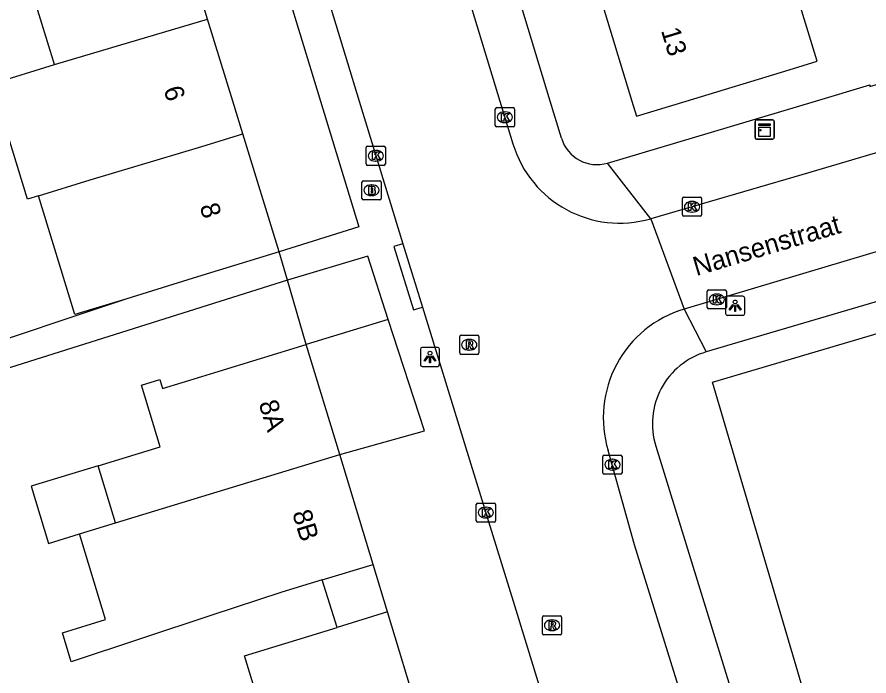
# Model space of a CAD drawing. Extents: x 161253 to 161848, y 384872 to 385383.
# Drawn here: x 161490.34 to 161534.89, y 384969.95 to 385004.39 of the extents above; entities that cross this region are included whole.
import ezdxf

# ---------------------------------------------------------------- set-up
doc = ezdxf.new("R2010")
doc.units = 0
for name, color, linetype in [('IMGEO_Brandkraan', 7, 'Continuous'), ('IMGEO_Hek', 7, 'Continuous'), ('IMGEO_Kast', 7, 'Continuous'), ('IMGEO_Kolk', 7, 'Continuous'), ('IMGEO_Lichtpunt', 7, 'Continuous'), ('IMGEO_Openbare_ruimte_label', 7, 'Continuous'), ('IMGEO_Pand', 7, 'Continuous'), ('IMGEO_Pand_nummerreeks', 7, 'Continuous'), ('IMGEO_Rijbaan_lokaal_open', 7, 'Continuous'), ('IMGEO_Rioolput', 7, 'Continuous'), ('IMGEO_Voetpad_open', 7, 'Continuous')]:
    doc.layers.add(name, color=color, linetype=linetype)

msp = doc.modelspace()

# ---------------------------------------------------------------- linework, layer by layer
at = {"layer": 'IMGEO_Brandkraan'}
for p, q in [((161508.378, 384994.912), (161508.378, 384995.764)), ((161508.453, 384995.838), (161509.305, 384995.838)), ((161509.379, 384995.764), (161509.379, 384994.912)), ((161508.866, 384995.618), (161508.891, 384995.618)), ((161509.305, 384994.838), (161508.453, 384994.838)), ((161508.889, 384995.058), (161508.864, 384995.058))]:
    msp.add_line(p, q, dxfattribs=at)
for points in [[(161508.378, 384994.912), (161508.378, 384995.764)], [(161508.453, 384995.838), (161509.305, 384995.838)], [(161509.379, 384995.764), (161509.379, 384994.912)], [(161508.726, 384995.538), (161508.726, 384995.138), (161508.939, 384995.138)], [(161508.957, 384995.538), (161508.726, 384995.538)], [(161508.905, 384995.457), (161508.851, 384995.457), (161508.851, 384995.381)], [(161508.851, 384995.381), (161508.904, 384995.381)], [(161508.913, 384995.305), (161508.851, 384995.305), (161508.851, 384995.224)], [(161508.851, 384995.224), (161508.913, 384995.224)], [(161509.305, 384994.838), (161508.453, 384994.838)]]:
    msp.add_lwpolyline(points, dxfattribs=at)
for centre, radius, start, end in [((161508.455, 384995.762), 0.0765, 91.552, 178.448), ((161508.455, 384995.762), 0.0765, 91.552, 178.448), ((161509.303, 384995.762), 0.0765, 1.552, 88.448), ((161509.303, 384995.762), 0.0765, 1.552, 88.448), ((161508.906, 384995.419), 0.0379, 267.8285, 90.9355), ((161508.914, 384995.264), 0.0404, 269.8759, 90.5077), ((161508.961, 384995.393), 0.145, 59.4692, 91.5367), ((161508.986, 384995.44), 0.0922, 285.5137, 58.1501), ((161508.991, 384995.248), 0.105, 301.3115, 78.989), ((161508.455, 384994.914), 0.0765, 181.552, 268.448), ((161508.455, 384994.914), 0.0765, 181.552, 268.448), ((161508.945, 384995.389), 0.251, 268.6676, 293.5347), ((161509.303, 384994.914), 0.0765, 271.552, 358.448), ((161509.303, 384994.914), 0.0765, 271.552, 358.448)]:
    msp.add_arc(centre, radius, start, end, dxfattribs=at)
for centre, major_axis, ratio, start_param, end_param in [((161508.865, 384995.338), (-0.387, 0.002), 0.722429, 4.712389, 7.853982), ((161508.89, 384995.338), (-0.39, 0.002), 0.717154, 1.570796, 4.712389)]:
    msp.add_ellipse(centre, major_axis=major_axis, ratio=ratio, start_param=start_param, end_param=end_param, dxfattribs=at)
at = {"layer": 'IMGEO_Hek'}
msp.add_lwpolyline([(161507.075, 384972.487), (161506.304, 384974.971)], dxfattribs=at)
at = {"layer": 'IMGEO_Kast'}
for p, q in [((161528.929, 384998.089), (161528.929, 384998.93)), ((161528.929, 384998.93), (161528.929, 384998.089)), ((161529.004, 384999.014), (161529.845, 384999.014)), ((161529.845, 384999.014), (161529.004, 384999.014)), ((161529.929, 384998.939), (161529.929, 384998.098)), ((161529.929, 384998.098), (161529.929, 384998.939)), ((161529.854, 384998.014), (161529.013, 384998.014)), ((161529.013, 384998.014), (161529.854, 384998.014))]:
    msp.add_line(p, q, dxfattribs=at)
for points in [[(161529.124, 384998.804), (161529.724, 384998.804), (161529.724, 384998.719), (161529.124, 384998.719), (161529.124, 384998.804)], [(161529.124, 384998.629), (161529.724, 384998.629), (161529.724, 384998.14), (161529.124, 384998.14), (161529.124, 384998.629)]]:
    msp.add_lwpolyline(points, dxfattribs=at)
msp.add_circle((161529.208, 384998.478), 0.0377, dxfattribs=at)
for centre, start, end in [((161529.007, 384998.936), 92.4484, 184.2845), ((161529.007, 384998.936), 92.4484, 184.2845), ((161529.851, 384998.936), 2.4484, 94.2845), ((161529.851, 384998.936), 2.4484, 94.2845), ((161529.007, 384998.092), 182.4484, 274.2845), ((161529.007, 384998.092), 182.4484, 274.2845), ((161529.851, 384998.092), 272.4484, 4.2845), ((161529.851, 384998.092), 272.4484, 4.2845)]:
    msp.add_arc(centre, 0.0779, start, end, dxfattribs=at)
at = {"layer": 'IMGEO_Kolk'}
for p, q in [((161515.425, 384999.657), (161516.277, 384999.657)), ((161515.35, 384998.731), (161515.35, 384999.583)), ((161515.838, 384999.437), (161515.863, 384999.437)), ((161516.351, 384999.583), (161516.351, 384998.731)), ((161515.861, 384998.877), (161515.836, 384998.877)), ((161516.277, 384998.657), (161515.425, 384998.657)), ((161508.601, 384996.714), (161508.601, 384997.566)), ((161508.676, 384997.64), (161509.528, 384997.64)), ((161509.602, 384997.566), (161509.602, 384996.714)), ((161509.089, 384997.42), (161509.114, 384997.42)), ((161509.528, 384996.64), (161508.676, 384996.64)), ((161509.112, 384996.86), (161509.087, 384996.86)), ((161525.134, 384994.051), (161525.134, 384994.903)), ((161525.209, 384994.977), (161526.061, 384994.977)), ((161525.622, 384994.757), (161525.647, 384994.757)), ((161526.135, 384994.903), (161526.135, 384994.051)), ((161526.061, 384993.977), (161525.209, 384993.977)), ((161525.645, 384994.197), (161525.62, 384994.197)), ((161526.431, 384989.209), (161526.431, 384990.061)), ((161526.506, 384990.135), (161527.358, 384990.135)), ((161526.919, 384989.915), (161526.944, 384989.915)), ((161527.432, 384990.061), (161527.432, 384989.209)), ((161527.358, 384989.135), (161526.506, 384989.135)), ((161526.942, 384989.355), (161526.917, 384989.355)), ((161520.973, 384980.571), (161520.973, 384981.423)), ((161521.048, 384981.497), (161521.9, 384981.497)), ((161521.974, 384981.423), (161521.974, 384980.571)), ((161521.461, 384981.277), (161521.486, 384981.277)), ((161521.484, 384980.717), (161521.459, 384980.717)), ((161521.9, 384980.497), (161521.048, 384980.497)), ((161514.356, 384978.066), (161514.356, 384978.918)), ((161514.431, 384978.992), (161515.283, 384978.992)), ((161514.844, 384978.772), (161514.869, 384978.772)), ((161515.357, 384978.918), (161515.357, 384978.066)), ((161515.283, 384977.992), (161514.431, 384977.992)), ((161514.867, 384978.212), (161514.842, 384978.212))]:
    msp.add_line(p, q, dxfattribs=at)
for points in [[(161515.425, 384999.657), (161516.277, 384999.657)], [(161515.35, 384998.731), (161515.35, 384999.583)], [(161515.671, 384999.357), (161515.794, 384999.357), (161515.794, 384999.206), (161515.924, 384999.357), (161516.088, 384999.357), (161515.942, 384999.206), (161516.095, 384998.957), (161515.943, 384998.957), (161515.858, 384999.121), (161515.794, 384999.054), (161515.794, 384998.957), (161515.671, 384998.957), (161515.671, 384999.357)], [(161516.351, 384999.583), (161516.351, 384998.731)], [(161516.277, 384998.657), (161515.425, 384998.657)], [(161508.601, 384996.714), (161508.601, 384997.566)], [(161508.676, 384997.64), (161509.528, 384997.64)], [(161509.602, 384997.566), (161509.602, 384996.714)], [(161508.922, 384997.34), (161509.045, 384997.34), (161509.045, 384997.189), (161509.175, 384997.34), (161509.339, 384997.34), (161509.193, 384997.189), (161509.346, 384996.94), (161509.194, 384996.94), (161509.109, 384997.104), (161509.045, 384997.037), (161509.045, 384996.94), (161508.922, 384996.94), (161508.922, 384997.34)], [(161509.528, 384996.64), (161508.676, 384996.64)], [(161525.134, 384994.051), (161525.134, 384994.903)], [(161525.209, 384994.977), (161526.061, 384994.977)], [(161526.135, 384994.903), (161526.135, 384994.051)], [(161525.455, 384994.677), (161525.578, 384994.677), (161525.578, 384994.526), (161525.708, 384994.677), (161525.872, 384994.677), (161525.726, 384994.526), (161525.879, 384994.277), (161525.727, 384994.277), (161525.642, 384994.441), (161525.578, 384994.374), (161525.578, 384994.277), (161525.455, 384994.277), (161525.455, 384994.677)], [(161526.061, 384993.977), (161525.209, 384993.977)], [(161526.431, 384989.209), (161526.431, 384990.061)], [(161526.506, 384990.135), (161527.358, 384990.135)], [(161527.432, 384990.061), (161527.432, 384989.209)], [(161526.752, 384989.835), (161526.875, 384989.835), (161526.875, 384989.684), (161527.005, 384989.835), (161527.169, 384989.835), (161527.023, 384989.684), (161527.176, 384989.435), (161527.024, 384989.435), (161526.939, 384989.599), (161526.875, 384989.532), (161526.875, 384989.435), (161526.752, 384989.435), (161526.752, 384989.835)], [(161527.358, 384989.135), (161526.506, 384989.135)], [(161520.973, 384980.571), (161520.973, 384981.423)], [(161521.048, 384981.497), (161521.9, 384981.497)], [(161521.974, 384981.423), (161521.974, 384980.571)], [(161521.294, 384981.197), (161521.417, 384981.197), (161521.417, 384981.046), (161521.547, 384981.197), (161521.711, 384981.197), (161521.565, 384981.046), (161521.718, 384980.797), (161521.566, 384980.797), (161521.481, 384980.961), (161521.417, 384980.894), (161521.417, 384980.797), (161521.294, 384980.797), (161521.294, 384981.197)], [(161521.9, 384980.497), (161521.048, 384980.497)], [(161514.356, 384978.066), (161514.356, 384978.918)], [(161514.431, 384978.992), (161515.283, 384978.992)], [(161515.357, 384978.918), (161515.357, 384978.066)], [(161514.677, 384978.692), (161514.8, 384978.692), (161514.8, 384978.541), (161514.93, 384978.692), (161515.094, 384978.692), (161514.948, 384978.541), (161515.101, 384978.292), (161514.949, 384978.292), (161514.864, 384978.456), (161514.8, 384978.389), (161514.8, 384978.292), (161514.677, 384978.292), (161514.677, 384978.692)], [(161515.283, 384977.992), (161514.431, 384977.992)]]:
    msp.add_lwpolyline(points, dxfattribs=at)
for centre, start, end in [((161515.427, 384999.581), 91.552, 178.448), ((161515.427, 384999.581), 91.552, 178.448), ((161516.275, 384999.581), 1.552, 88.448), ((161516.275, 384999.581), 1.552, 88.448), ((161515.427, 384998.733), 181.552, 268.448), ((161515.427, 384998.733), 181.552, 268.448), ((161516.275, 384998.733), 271.552, 358.448), ((161516.275, 384998.733), 271.552, 358.448), ((161508.678, 384997.564), 91.552, 178.448), ((161508.678, 384997.564), 91.552, 178.448), ((161509.526, 384997.564), 1.552, 88.448), ((161509.526, 384997.564), 1.552, 88.448), ((161508.678, 384996.716), 181.552, 268.448), ((161508.678, 384996.716), 181.552, 268.448), ((161509.526, 384996.716), 271.552, 358.448), ((161509.526, 384996.716), 271.552, 358.448), ((161525.211, 384994.901), 91.552, 178.448), ((161525.211, 384994.901), 91.552, 178.448), ((161526.059, 384994.901), 1.552, 88.448), ((161526.059, 384994.901), 1.552, 88.448), ((161525.211, 384994.053), 181.552, 268.448), ((161525.211, 384994.053), 181.552, 268.448), ((161526.059, 384994.053), 271.552, 358.448), ((161526.059, 384994.053), 271.552, 358.448), ((161526.508, 384990.059), 91.552, 178.448), ((161526.508, 384990.059), 91.552, 178.448), ((161527.356, 384990.059), 1.552, 88.448), ((161527.356, 384990.059), 1.552, 88.448), ((161526.508, 384989.211), 181.552, 268.448), ((161526.508, 384989.211), 181.552, 268.448), ((161527.356, 384989.211), 271.552, 358.448), ((161527.356, 384989.211), 271.552, 358.448), ((161521.05, 384981.421), 91.552, 178.448), ((161521.05, 384981.421), 91.552, 178.448), ((161521.898, 384981.421), 1.552, 88.448), ((161521.898, 384981.421), 1.552, 88.448), ((161521.05, 384980.573), 181.552, 268.448), ((161521.05, 384980.573), 181.552, 268.448), ((161521.898, 384980.573), 271.552, 358.448), ((161521.898, 384980.573), 271.552, 358.448), ((161514.433, 384978.916), 91.552, 178.448), ((161514.433, 384978.916), 91.552, 178.448), ((161515.281, 384978.916), 1.552, 88.448), ((161515.281, 384978.916), 1.552, 88.448), ((161514.433, 384978.068), 181.552, 268.448), ((161514.433, 384978.068), 181.552, 268.448), ((161515.281, 384978.068), 271.552, 358.448), ((161515.281, 384978.068), 271.552, 358.448)]:
    msp.add_arc(centre, 0.0765, start, end, dxfattribs=at)
for centre, major_axis, ratio, start_param, end_param in [((161515.837, 384999.157), (-0.387, 0.002), 0.722429, 4.712389, 7.853982), ((161515.862, 384999.157), (-0.39, 0.002), 0.717154, 1.570796, 4.712389), ((161509.088, 384997.14), (-0.387, 0.002), 0.722429, 4.712389, 7.853982), ((161509.113, 384997.14), (-0.39, 0.002), 0.717154, 1.570796, 4.712389), ((161525.621, 384994.477), (-0.387, 0.002), 0.722429, 4.712389, 7.853982), ((161525.646, 384994.477), (-0.39, 0.002), 0.717154, 1.570796, 4.712389), ((161526.918, 384989.635), (-0.387, 0.002), 0.722429, 4.712389, 7.853982), ((161526.943, 384989.635), (-0.39, 0.002), 0.717154, 1.570796, 4.712389), ((161521.46, 384980.997), (-0.387, 0.002), 0.722429, 4.712389, 7.853982), ((161521.485, 384980.997), (-0.39, 0.002), 0.717154, 1.570796, 4.712389), ((161514.843, 384978.492), (-0.387, 0.002), 0.722429, 4.712389, 7.853982), ((161514.868, 384978.492), (-0.39, 0.002), 0.717154, 1.570796, 4.712389)]:
    msp.add_ellipse(centre, major_axis=major_axis, ratio=ratio, start_param=start_param, end_param=end_param, dxfattribs=at)
at = {"layer": 'IMGEO_Lichtpunt'}
for p, q in [((161527.393, 384989.703), (161527.393, 384988.896)), ((161527.393, 384989.703), (161527.393, 384988.896)), ((161528.295, 384989.798), (161527.487, 384989.798)), ((161528.295, 384989.798), (161527.487, 384989.798)), ((161528.389, 384988.896), (161528.389, 384989.703)), ((161528.389, 384988.896), (161528.389, 384989.703)), ((161527.487, 384988.802), (161528.295, 384988.802)), ((161527.487, 384988.802), (161528.295, 384988.802)), ((161511.436, 384987.029), (161511.436, 384986.222)), ((161511.436, 384987.029), (161511.436, 384986.222)), ((161512.338, 384987.124), (161511.53, 384987.124)), ((161512.338, 384987.124), (161511.53, 384987.124)), ((161512.432, 384986.222), (161512.432, 384987.029)), ((161512.432, 384986.222), (161512.432, 384987.029)), ((161511.53, 384986.128), (161512.338, 384986.128)), ((161511.53, 384986.128), (161512.338, 384986.128))]:
    msp.add_line(p, q, dxfattribs=at)
for points in [[(161527.767, 384989.367), (161527.806, 384989.339), (161527.618, 384989.077), (161527.58, 384989.104), (161527.767, 384989.367)], [(161527.869, 384989.319), (161527.916, 384989.319), (161527.916, 384988.997), (161527.869, 384988.997), (161527.869, 384989.319)], [(161527.979, 384989.339), (161528.017, 384989.366), (161528.204, 384989.104), (161528.165, 384989.076), (161527.979, 384989.339)], [(161511.81, 384986.693), (161511.849, 384986.665), (161511.661, 384986.403), (161511.623, 384986.43), (161511.81, 384986.693)], [(161511.912, 384986.645), (161511.959, 384986.645), (161511.959, 384986.323), (161511.912, 384986.323), (161511.912, 384986.645)], [(161512.022, 384986.665), (161512.06, 384986.692), (161512.247, 384986.43), (161512.208, 384986.402), (161512.022, 384986.665)]]:
    msp.add_lwpolyline(points, dxfattribs=at)
for centre in [(161527.892, 384989.501), (161511.935, 384986.827)]:
    msp.add_circle(centre, 0.0994, dxfattribs=at)
for centre, start, end in [((161527.487, 384989.703), 90, 180), ((161527.487, 384989.703), 90, 180), ((161528.295, 384989.703), 0, 90), ((161528.295, 384989.703), 0, 90), ((161527.487, 384988.896), 180, 270), ((161527.487, 384988.896), 180, 270), ((161528.295, 384988.896), 270, 0), ((161528.295, 384988.896), 270, 360), ((161511.53, 384987.029), 90, 180), ((161511.53, 384987.029), 90, 180), ((161512.338, 384987.029), 0, 90), ((161512.338, 384987.029), 0, 90), ((161511.53, 384986.222), 180, 270), ((161511.53, 384986.222), 180, 270), ((161512.338, 384986.222), 270, 0), ((161512.338, 384986.222), 270, 360)]:
    msp.add_arc(centre, 0.0946, start, end, dxfattribs=at)
at = {"layer": 'IMGEO_Pand'}
for points in [[(161500.299, 385004.283), (161500, 385005.255), (161498.443, 385010.31)], [(161492.311, 385001.903), (161490.476, 385007.857)], [(161520.856, 385005.389), (161522.493, 385000), (161522.733, 384999.21), (161525.334, 385000), (161530.719, 385001.636), (161532.174, 385002.078), (161531.166, 385005.396), (161529.711, 385004.954), (161528.842, 385007.815)], [(161492.311, 385001.903), (161500, 385004.194), (161500.299, 385004.283)], [(161502.147, 384998.285), (161501.619, 385000), (161500.299, 385004.283)], [(161491.462, 384995.042), (161490.89, 384994.866), (161489.308, 385000), (161489.033, 385000.893), (161492.311, 385001.903)], [(161491.462, 384995.042), (161494.168, 384995.875), (161500, 384997.623), (161502.147, 384998.285)], [(161504.045, 384992.126), (161502.147, 384998.285)], [(161551.077, 384978.837), (161549.692, 384983.529), (161546.066, 384982.466), (161554.584, 384953.632), (161537.526, 384948.588), (161526.699, 384985.306), (161543.744, 384990.345), (161544.689, 384987.166), (161579.135, 384997.334), (161581.889, 384987.932), (161551.077, 384978.837)], [(161496.079, 384989.672), (161493.374, 384988.838), (161491.462, 384995.042)], [(161504.045, 384992.126), (161500, 384990.881), (161499.267, 384990.655), (161496.079, 384989.672)], [(161494.582, 384980.94), (161497.831, 384981.929), (161496.849, 384985.156), (161497.81, 384985.449), (161497.952, 384984.982), (161500, 384985.606), (161500.689, 384985.816), (161505.463, 384987.269)], [(161507.221, 384981.529), (161505.463, 384987.269)], [(161495.492, 384977.952), (161500, 384979.327), (161507.221, 384981.529)], [(161508.971, 384975.783), (161507.221, 384981.529)], [(161494.582, 384980.94), (161491.076, 384979.873), (161491.987, 384976.883), (161493.602, 384977.376)], [(161495.492, 384977.952), (161494.582, 384980.94)], [(161493.602, 384977.376), (161495.492, 384977.952)], [(161506.304, 384974.971), (161504.188, 384974.327), (161500.484, 384973.106), (161493.176, 384970.697), (161492.714, 384972.216), (161494.965, 384972.902), (161493.602, 384977.376)], [(161506.304, 384974.971), (161508.971, 384975.783)], [(161509.721, 384973.301), (161507.075, 384972.487)], [(161522.893, 384929.534), (161521.803, 384933.798), (161520.157, 384939.183), (161519.947, 384939.116), (161511.174, 384967.775), (161511.374, 384967.836), (161509.721, 384973.301)], [(161519.549, 384923.787), (161518.264, 384923.399), (161518.795, 384921.665), (161515.363, 384920.585), (161514.893, 384922.08), (161514.313, 384923.924), (161512.548, 384923.369), (161513.118, 384921.556), (161506.175, 384919.505), (161506.097, 384919.759), (161500.675, 384937.542), (161502.711, 384938.153), (161495.035, 384963.886), (161503.638, 384966.452), (161502.241, 384971.001), (161507.075, 384972.487)]]:
    msp.add_lwpolyline(points, dxfattribs=at)
at = {"layer": 'IMGEO_Rijbaan_lokaal_open'}
for points in [[(161504.114, 385037.727), (161515.595, 385000), (161516.273, 384997.762)], [(161502.25, 385019.651), (161508.229, 385000), (161508.817, 384998.066), (161510.523, 384992.54)], [(161644.123, 384999.737), (161641.51, 385000), (161585.261, 385005.661), (161583.856, 385005.737), (161582.451, 385005.688), (161581.055, 385005.513), (161579.681, 385005.214), (161579.302, 385005.109), (161561.812, 385000), (161542.1, 384994.163), (161525.218, 384989.124)], [(161541.648, 384999.183), (161531.372, 384996.139), (161523.482, 384993.851)], [(161523.482, 384993.851), (161525.218, 384989.124)], [(161510.523, 384992.54), (161511.544, 384989.229)], [(161511.544, 384989.229), (161515, 384978.034), (161516.286, 384973.865), (161517.721, 384969.216), (161519.126, 384964.664), (161520.819, 384959.179), (161522.041, 384955.193), (161523.494, 384950.456), (161528.945, 384932.684), (161529.409, 384932.835), (161530.162, 384930.325), (161529.71, 384930.189), (161530.583, 384927.343), (161532.615, 384920.743)], [(161531.609, 384947.582), (161526.629, 384963.906), (161526.271, 384965.078), (161522.626, 384976.815), (161521.248, 384981.738)]]:
    msp.add_lwpolyline(points, dxfattribs=at)
for centre, radius, start, end in [((161521.856, 384999.454), 5.834, 196.8565, 286.1824), ((161526.911, 384983.454), 5.917, 106.6225, 196.8611)]:
    msp.add_arc(centre, radius, start, end, dxfattribs=at)
at = {"layer": 'IMGEO_Rioolput'}
for p, q in [((161513.487, 384986.836), (161513.487, 384987.688)), ((161513.562, 384987.762), (161514.414, 384987.762)), ((161514.488, 384987.688), (161514.488, 384986.836)), ((161513.975, 384987.542), (161514, 384987.542)), ((161514.414, 384986.762), (161513.562, 384986.762)), ((161513.998, 384986.982), (161513.973, 384986.982)), ((161517.814, 384972.177), (161517.814, 384973.029)), ((161517.889, 384973.103), (161518.741, 384973.103)), ((161518.815, 384973.029), (161518.815, 384972.177)), ((161518.302, 384972.883), (161518.327, 384972.883)), ((161518.741, 384972.103), (161517.889, 384972.103)), ((161518.325, 384972.323), (161518.3, 384972.323))]:
    msp.add_line(p, q, dxfattribs=at)
for points in [[(161513.487, 384986.836), (161513.487, 384987.688)], [(161513.562, 384987.762), (161514.414, 384987.762)], [(161514.488, 384987.688), (161514.488, 384986.836)], [(161514.076, 384987.46), (161513.824, 384987.462), (161513.824, 384987.062)], [(161513.824, 384987.062), (161513.948, 384987.062), (161513.948, 384987.224), (161513.959, 384987.224)], [(161514.002, 384987.381), (161513.948, 384987.381), (161513.948, 384987.3)], [(161513.948, 384987.3), (161514, 384987.3)], [(161514.006, 384987.195), (161514.077, 384987.062), (161514.217, 384987.062), (161514.152, 384987.188)], [(161514.414, 384986.762), (161513.562, 384986.762)], [(161517.814, 384972.177), (161517.814, 384973.029)], [(161517.889, 384973.103), (161518.741, 384973.103)], [(161518.815, 384973.029), (161518.815, 384972.177)], [(161518.403, 384972.801), (161518.151, 384972.803), (161518.151, 384972.403)], [(161518.151, 384972.403), (161518.275, 384972.403), (161518.275, 384972.565), (161518.286, 384972.565)], [(161518.329, 384972.722), (161518.275, 384972.722), (161518.275, 384972.641)], [(161518.275, 384972.641), (161518.327, 384972.641)], [(161518.333, 384972.536), (161518.404, 384972.403), (161518.544, 384972.403), (161518.479, 384972.529)], [(161518.741, 384972.103), (161517.889, 384972.103)]]:
    msp.add_lwpolyline(points, dxfattribs=at)
for centre, radius, start, end in [((161513.564, 384987.686), 0.0765, 91.552, 178.448), ((161513.564, 384987.686), 0.0765, 91.552, 178.448), ((161514.412, 384987.686), 0.0765, 1.552, 88.448), ((161514.412, 384987.686), 0.0765, 1.552, 88.448), ((161513.958, 384987.171), 0.0533, 26.0293, 88.6989), ((161513.984, 384987.489), 0.19, 274.7715, 282.9687), ((161514.008, 384987.285), 0.0964, 77.0061, 93.1865), ((161514.022, 384987.342), 0.0378, 276.6634, 79.6772), ((161514.075, 384987.35), 0.109, 350.3612, 89.416), ((161514.073, 384987.35), 0.112, 277.5842, 350.9817), ((161514.057, 384987.135), 0.108, 29.5134, 73.7905), ((161513.564, 384986.838), 0.0765, 181.552, 268.448), ((161513.564, 384986.838), 0.0765, 181.552, 268.448), ((161514.412, 384986.838), 0.0765, 271.552, 358.448), ((161514.412, 384986.838), 0.0765, 271.552, 358.448), ((161517.891, 384973.027), 0.0765, 91.552, 178.448), ((161517.891, 384973.027), 0.0765, 91.552, 178.448), ((161518.739, 384973.027), 0.0765, 1.552, 88.448), ((161518.739, 384973.027), 0.0765, 1.552, 88.448), ((161518.285, 384972.512), 0.0533, 26.0293, 88.6989), ((161518.311, 384972.83), 0.19, 274.7715, 282.9687), ((161518.335, 384972.626), 0.0964, 77.0061, 93.1865), ((161518.349, 384972.683), 0.0378, 276.6634, 79.6772), ((161518.402, 384972.691), 0.109, 350.3612, 89.416), ((161518.4, 384972.691), 0.112, 277.5842, 350.9817), ((161518.384, 384972.476), 0.108, 29.5134, 73.7905), ((161517.891, 384972.179), 0.0765, 181.552, 268.448), ((161517.891, 384972.179), 0.0765, 181.552, 268.448), ((161518.739, 384972.179), 0.0765, 271.552, 358.448), ((161518.739, 384972.179), 0.0765, 271.552, 358.448)]:
    msp.add_arc(centre, radius, start, end, dxfattribs=at)
for centre, major_axis, ratio, start_param, end_param in [((161513.974, 384987.262), (-0.387, 0.002), 0.722429, 4.712389, 7.853982), ((161513.999, 384987.262), (-0.39, 0.002), 0.717154, 1.570796, 4.712389), ((161518.301, 384972.603), (-0.387, 0.002), 0.722429, 4.712389, 7.853982), ((161518.326, 384972.603), (-0.39, 0.002), 0.717154, 1.570796, 4.712389)]:
    msp.add_ellipse(centre, major_axis=major_axis, ratio=ratio, start_param=start_param, end_param=end_param, dxfattribs=at)
at = {"layer": 'IMGEO_Voetpad_open'}
for points in [[(161518.805, 384998.06), (161518.218, 385000), (161506.717, 385037.985)], [(161496.487, 385016.657), (161500, 385017.708), (161500.743, 385017.93), (161506.207, 385000), (161508.211, 384993.423), (161504.045, 384992.126)], [(161521.224, 384996.76), (161532.085, 385000), (161534.931, 385000.849), (161534.935, 385000.758), (161540.533, 385002.46), (161539.957, 385004.357)], [(161582.364, 385002.988), (161580.985, 385002.819), (161579.262, 385002.45), (161578.675, 385002.287), (161570.906, 385000), (161530.284, 384988.042), (161526.38, 384986.893)], [(161523.482, 384993.851), (161521.224, 384996.76)], [(161510.523, 384992.54), (161510.046, 384992.393), (161511.068, 384989.082), (161511.544, 384989.229)], [(161504.48, 384990.635), (161504.045, 384992.126)], [(161509.755, 384988.583), (161508.68, 384991.895), (161504.48, 384990.635)], [(161504.48, 384990.635), (161478.706, 384982.523)], [(161505.463, 384987.269), (161504.48, 384990.635)], [(161496.079, 384989.672), (161478.327, 384983.747)], [(161525.218, 384989.124), (161526.38, 384986.893)], [(161509.755, 384988.583), (161505.463, 384987.269)], [(161507.221, 384981.529), (161511.645, 384982.763), (161509.755, 384988.583)], [(161523.736, 384981.966), (161535.25, 384944.673), (161535.602, 384944.78), (161536.001, 384943.48), (161550.245, 384897.029)], [(161509.721, 384973.301), (161508.971, 384975.783)], [(161507.075, 384972.487), (161506.304, 384974.971)]]:
    msp.add_lwpolyline(points, dxfattribs=at)
for centre, radius, start, end in [((161520.668, 384998.626), 1.947, 196.8958, 286.5959), ((161527.489, 384983.125), 3.928, 106.4043, 197.1566)]:
    msp.add_arc(centre, radius, start, end, dxfattribs=at)

# ---------------------------------------------------------------- texts
at = {"layer": 'IMGEO_Openbare_ruimte_label'}
msp.add_text('Nansenstraat', height=1, rotation=16.6224, dxfattribs=at).set_placement((161525.859, 384990.849))
at = {"layer": 'IMGEO_Pand_nummerreeks'}
for s, rotation, p in [('13', 286.9003, (161524.005, 385003.691)), ('6', 287.1255, (161497.995, 385000.622)), ('8', 287.1255, (161499.883, 384994.499)), ('8A', 287.0283, (161502.97, 384984.207)), ('8B', 286.9364, (161504.724, 384978.47))]:
    msp.add_text(s, height=1, rotation=rotation, dxfattribs=at).set_placement(p)

doc.saveas('drawing.dxf')
